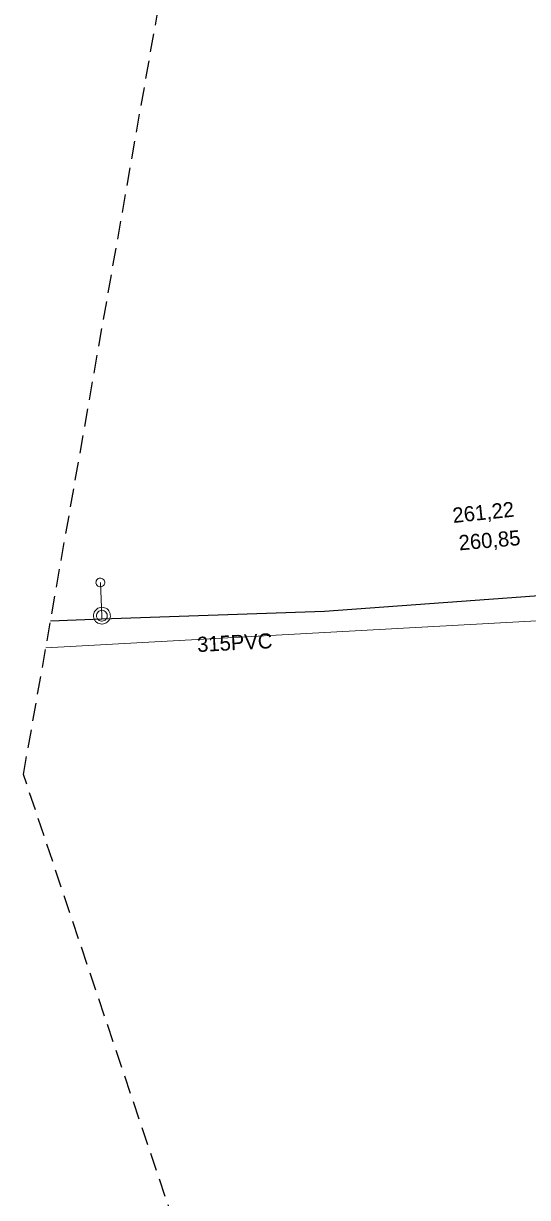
# Model space of a CAD drawing. Extents: x -732096 to -731933, y -1048703 to -1047964.
# Drawn here: x -732073.6 to -732046.9, y -1048069.5 to -1048007.3 of the extents above; entities that cross this region are included whole.
import ezdxf

# ---------------------------------------------------------------- set-up
doc = ezdxf.new("R2010")
doc.units = 0
doc.header["$LTSCALE"] = 0.32
doc.linetypes.add('MEDIUM_DASHED', pattern=[4.5, 3, -1.5])
doc.layers.add('1', color=7, linetype='Continuous')
for name, color, linetype, lineweight in [('20', 7, 'Continuous', 13), ('63', 7, 'MEDIUM_DASHED', 25), ('8', 7, 'Continuous', 13)]:
    doc.layers.add(name, color=color, linetype=linetype, lineweight=lineweight)

msp = doc.modelspace()

# ---------------------------------------------------------------- linework, layer by layer
at = {"layer": '20'}
msp.add_lwpolyline([(-732072.387, -1048040.394), (-732045.426, -1048038.914), (-732043.129, -1048038.788), (-732036.239, -1048038.41), (-732035.469, -1048028.56)], dxfattribs=at)
msp.add_lwpolyline([(-732072.387, -1048040.394), (-732045.426, -1048038.914), (-732043.129, -1048038.788), (-732036.239, -1048038.41), (-732035.469, -1048028.56)], dxfattribs=at)
at = {"layer": '63'}
msp.add_lwpolyline([(-732040.436, -1048145.923), (-732073.567, -1048047.117), (-732073.568, -1048047.115), (-732073.568, -1048047.114), (-732073.568, -1048047.112), (-732060.033, -1047970.086), (-732060.033, -1047970.084), (-732060.032, -1047970.082), (-732060.031, -1047970.081), (-732060.029, -1047970.079), (-732060.028, -1047970.078), (-732060.026, -1047970.078), (-732060.024, -1047970.077), (-732001.831, -1047964.038), (-732001.829, -1047964.038), (-732001.827, -1047964.038), (-732001.825, -1047964.039), (-732001.823, -1047964.04), (-732001.822, -1047964.041), (-732001.821, -1047964.043), (-732001.82, -1047964.045), (-732001.82, -1047964.047), (-731997.077, -1048043.55), (-731968.389, -1048129.387)], dxfattribs=at)
at = {"layer": '8'}
for points in [[(-732069.509, -1048036.708), (-732069.561, -1048036.716), (-732069.61, -1048036.735), (-732069.653, -1048036.765), (-732069.689, -1048036.804), (-732069.714, -1048036.85), (-732069.728, -1048036.901), (-732069.732, -1048036.953), (-732069.723, -1048037.004), (-732069.702, -1048037.053), (-732069.671, -1048037.096), (-732069.631, -1048037.129), (-732069.585, -1048037.154), (-732069.533, -1048037.167), (-732069.481, -1048037.168), (-732069.429, -1048037.159), (-732069.382, -1048037.136), (-732069.34, -1048037.104), (-732069.307, -1048037.063), (-732069.284, -1048037.016), (-732069.272, -1048036.965), (-732069.272, -1048036.913), (-732069.284, -1048036.861), (-732069.307, -1048036.814), (-732069.341, -1048036.773), (-732069.382, -1048036.742), (-732069.429, -1048036.719), (-732069.481, -1048036.709)], [(-732069.402, -1048039.145), (-732069.329, -1048039.136), (-732069.259, -1048039.116), (-732069.193, -1048039.084), (-732069.133, -1048039.042), (-732069.08, -1048038.991), (-732069.037, -1048038.932), (-732069.005, -1048038.867), (-732068.982, -1048038.797), (-732068.972, -1048038.725), (-732068.973, -1048038.651), (-732068.987, -1048038.579), (-732069.013, -1048038.51), (-732069.048, -1048038.447), (-732069.094, -1048038.39), (-732069.149, -1048038.341), (-732069.21, -1048038.302), (-732069.278, -1048038.274), (-732069.349, -1048038.256), (-732069.422, -1048038.251), (-732069.495, -1048038.258), (-732069.566, -1048038.276), (-732069.633, -1048038.306), (-732069.694, -1048038.346), (-732069.747, -1048038.396), (-732069.792, -1048038.454), (-732069.827, -1048038.518), (-732069.851, -1048038.587), (-732069.864, -1048038.659), (-732069.864, -1048038.732), (-732069.852, -1048038.805), (-732069.829, -1048038.874), (-732069.794, -1048038.939), (-732069.75, -1048038.997), (-732069.697, -1048039.048), (-732069.636, -1048039.088), (-732069.57, -1048039.119), (-732069.499, -1048039.137), (-732069.427, -1048039.145)], [(-732069.408, -1048038.984), (-732069.35, -1048038.976), (-732069.294, -1048038.956), (-732069.245, -1048038.926), (-732069.202, -1048038.885), (-732069.168, -1048038.838), (-732069.145, -1048038.784), (-732069.133, -1048038.727), (-732069.133, -1048038.668), (-732069.145, -1048038.611), (-732069.169, -1048038.557), (-732069.203, -1048038.509), (-732069.245, -1048038.47), (-732069.295, -1048038.439), (-732069.351, -1048038.419), (-732069.409, -1048038.412), (-732069.467, -1048038.416), (-732069.524, -1048038.432), (-732069.576, -1048038.459), (-732069.621, -1048038.496), (-732069.658, -1048038.542), (-732069.684, -1048038.594), (-732069.7, -1048038.65), (-732069.704, -1048038.709), (-732069.696, -1048038.766), (-732069.677, -1048038.822), (-732069.646, -1048038.872), (-732069.605, -1048038.914), (-732069.558, -1048038.947), (-732069.504, -1048038.97), (-732069.447, -1048038.982)]]:
    msp.add_lwpolyline(points, close=True, dxfattribs=at)
msp.add_lwpolyline([(-732069.423, -1048038.886), (-732069.43, -1048038.7), (-732069.493, -1048036.94)], dxfattribs=at)
at = {"layer": '8', "lineweight": 25}
msp.add_lwpolyline([(-732044.829, -1048037.53), (-732057.629, -1048038.48), (-732069.423, -1048038.886), (-732072.139, -1048038.979)], dxfattribs=at)

# ---------------------------------------------------------------- texts
at = {"layer": '1'}
for s, rotation, p in [('261,22', 6, (-732050.818, -1048033.786)), ('260,85', 5, (-732050.499, -1048035.238)), ('315PVC', 3, (-732064.358, -1048040.624))]:
    msp.add_text(s, height=0.8, rotation=rotation, dxfattribs=at).set_placement(p)

doc.saveas('drawing.dxf')
